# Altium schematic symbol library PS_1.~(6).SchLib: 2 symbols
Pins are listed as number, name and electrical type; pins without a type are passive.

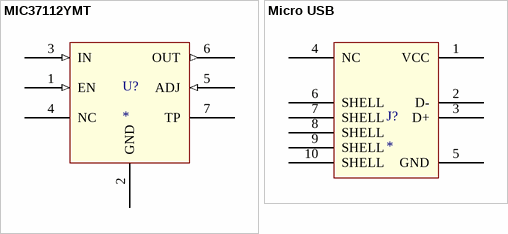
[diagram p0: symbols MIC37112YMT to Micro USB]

## MIC37112YMT
designator U?
LDO, 1A
pins: 1 EN (in), 2 GND (power), 3 IN (in), 4 NC (power), 5 ADJ (in), 6 OUT (out), 7 TP (power)

## Micro USB
designator J?
type B
pins: 1 VCC (power), 2 D- (power), 3 D+ (power), 4 NC (power), 5 GND (power), 6 SHELL (power), 7 SHELL (power), 8 SHELL (power), 9 SHELL (power), 10 SHELL (power)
